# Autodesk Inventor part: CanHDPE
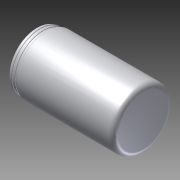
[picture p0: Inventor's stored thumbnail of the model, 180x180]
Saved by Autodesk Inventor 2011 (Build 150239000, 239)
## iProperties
Created: 2014-03
Part Number: CanHDPE
Document SubType Name: Modeling
Designer: Evgeny
Density: 1 g/cm^3
Author: Evgeny
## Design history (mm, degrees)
sketch "Эскиз1"
  geometry: L1 (0, 0)-(0, 38); L2 (-8, 46)-(-149, 46); L3 (-151, 44)-(-151, 43.5); L4 (-165, 41.5)-(-165, 38); L5 (-165, 38)-(-164, 38); L6 (-164, 38)-(-164, 41.5); L7 (-163.5, 42)-(-151, 42); L8 (-150, 43)-(-150, 44); L9 (-149, 45)-(-8, 45); L10 (-1, 38)-(-1, 0); L11 (-1, 0)-(0, 0); L12 (-160, 43)-(-160, 43.5); L13 (-160.5, 44)-(-160.5, 44); L14 (-161, 43.5)-(-161, 43); L15 (-155, 43)-(-155, 43.5); L16 (-155.5, 44)-(-155.5, 44); L17 (-156, 43.5)-(-156, 43); L18 (-161, 43)-(-163.5, 43); L19 (-151.5, 43)-(-155, 43); L20 (-156, 43)-(-160, 43); A1 r 2 centre (-149, 44) between (-149, 46) and (-151, 44); A2 r 1 centre (-149, 44) between (-149, 45) and (-150, 44); A3 r 1 centre (-151, 43) between (-151, 42) and (-150, 43); A4 r 7 centre (-8, 38) between (-1, 38) and (-8, 45); A5 r 8 centre (-8, 38) between (0, 38) and (-8, 46); A6 r 1.5 centre (-163.5, 41.5) between (-163.5, 43) and (-165, 41.5); A7 r 0.5 centre (-163.5, 41.5) between (-163.5, 42) and (-164, 41.5); A8 r 0.5 centre (-151.5, 43.5) between (-151.5, 43) and (-151, 43.5); A9 r 0.5 centre (-160.5, 43.5) between (-160.5, 44) and (-161, 43.5); A10 r 0.5 centre (-160.5, 43.5) between (-160, 43.5) and (-160.5, 44); A11 r 0.5 centre (-155.5, 43.5) between (-155.5, 44) and (-156, 43.5); A12 r 0.5 centre (-155.5, 43.5) between (-155, 43.5) and (-155.5, 44); 4 further points
  constraints: 40 end point, 28 tangent, 24 point on circle, 13 parallel, 12 centre point, 5 equal radius, 5 point on line, 1 perpendicular, 1 vertical
  dimensions: "d0" = 1 distance between parallel lines of L1 L10; "d1" = 1 distance between parallel lines of L9 L2; "d2" = 1 distance between parallel lines of L8 L3; "d4" = 1 distance between parallel lines of L6 L4; "d5" = 46 distance between parallel lines of L2 L11; "d6" = 165 distance between parallel lines of L1 L4; "d7" = 14 distance between parallel lines of L3 L4; "d9" = 38 distance between parallel lines of L5 L11; "d11" = 1 radius of A2; "d14" = 2 radius of A1 (derived); "d15" = 7 radius of A4; "d16" = 8 radius of A5; "d17" = 1.5 radius of A6; "d18" = 0.5 radius of A7; "d19" = 1 distance between parallel lines of L12 L14; "d20" = 1 distance between parallel lines of L15 L17; "d21" = 4 distance between parallel lines of L14 L4; "d22" = 4 distance between parallel lines of L17 L12; "d23" = 0.5 radius of A9
revolve "Вращение1" sketch "Эскиз1" stored, may be unused: angle "d12" = 90 deg
node "Твердое тело1"
other parameters: "d3" = 1, "d8" = 43
